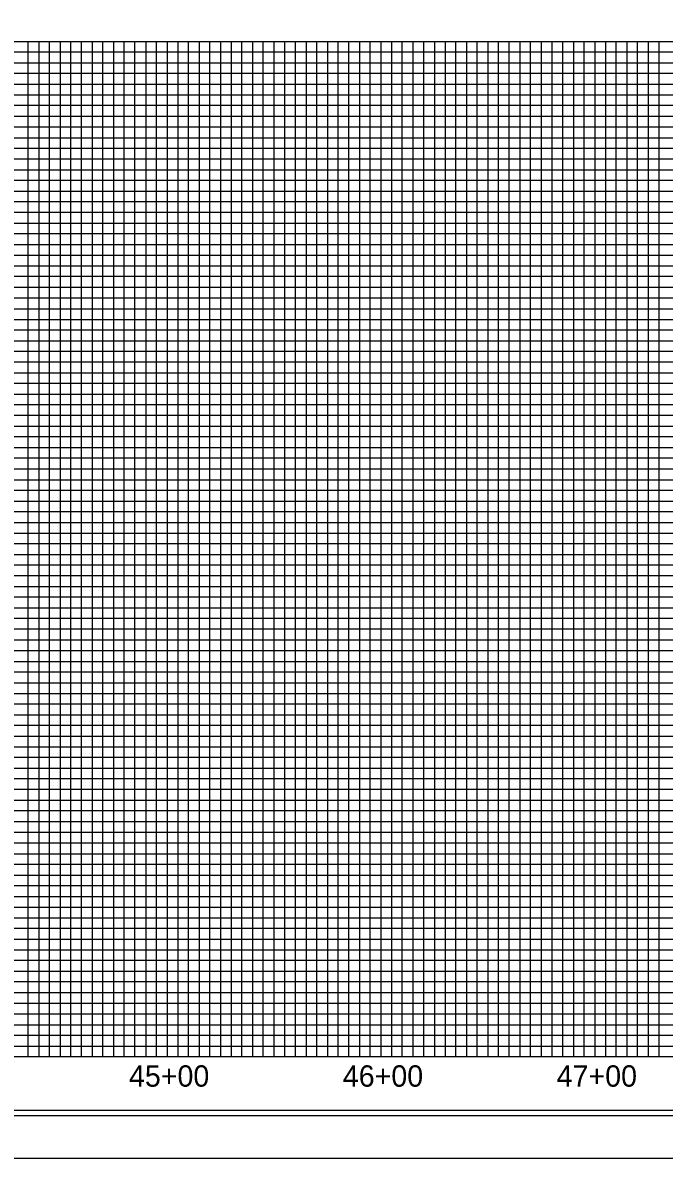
# Model space of a CAD drawing. Extents: x 0 to 7954, y -383 to 1504.
# Drawn here: x 1.851 to 2.351, y 0.008 to 0.894 of the extents above; entities that cross this region are included whole.
import ezdxf

# ---------------------------------------------------------------- set-up
doc = ezdxf.new("R2010")
doc.units = 0
for name, color, linetype in [('Sheet Profile Grid Major CELL', 7, 'Continuous'), ('Sheet Profile Grid Middle', 7, 'Continuous'), ('Sheet Profile Grid Minor CELL', 7, 'Continuous'), ('UC Plan Profile Sheet 34 CELL', 7, 'Continuous')]:
    doc.layers.add(name, color=color, linetype=linetype)

msp = doc.modelspace()

# ---------------------------------------------------------------- linework, layer by layer
at = {"layer": 'Sheet Profile Grid Major CELL'}
for points in [[(0.30499, 0.87916), (2.59666, 0.87916)], [(1.88833, 0.0875), (1.88833, 0.87916), (1.97166, 0.87916), (1.97166, 0.0875)], [(2.05499, 0.0875), (2.05499, 0.87916), (2.13833, 0.87916), (2.13833, 0.0875)], [(2.22166, 0.0875), (2.22166, 0.87916), (2.30499, 0.87916), (2.30499, 0.0875)], [(2.80499, 0.79583), (0.30499, 0.79583), (0.30499, 0.7125), (2.80499, 0.7125)], [(2.80499, 0.62916), (0.30499, 0.62916), (0.30499, 0.54583), (2.80499, 0.54583)], [(2.80499, 0.4625), (0.30499, 0.4625), (0.30499, 0.37916), (2.80499, 0.37916)], [(2.80499, 0.29583), (0.30499, 0.29583), (0.30499, 0.2125), (2.80499, 0.2125)], [(2.80499, 0.12916), (0.30499, 0.12916)]]:
    msp.add_lwpolyline(points, dxfattribs=at)
at = {"layer": 'Sheet Profile Grid Middle'}
for p, q in [((0.30499, 0.8375), (2.59666, 0.8375)), ((2.80499, 0.75416), (0.30499, 0.75416)), ((0.30499, 0.67083), (2.80499, 0.67083)), ((2.80499, 0.5875), (0.30499, 0.5875)), ((0.30499, 0.50416), (2.80499, 0.50416)), ((2.80499, 0.42083), (0.30499, 0.42083)), ((0.30499, 0.3375), (2.80499, 0.3375)), ((2.80499, 0.25416), (0.30499, 0.25416)), ((0.30499, 0.17083), (2.80499, 0.17083))]:
    msp.add_line(p, q, dxfattribs=at)
for points in [[(1.92999, 0.0875), (1.92999, 0.87916), (2.01333, 0.87916), (2.01333, 0.0875)], [(2.09666, 0.0875), (2.09666, 0.87916), (2.17999, 0.87916), (2.17999, 0.0875)], [(2.26333, 0.0875), (2.26333, 0.87916), (2.34666, 0.87916), (2.34666, 0.0875)]]:
    msp.add_lwpolyline(points, dxfattribs=at)
at = {"layer": 'Sheet Profile Grid Minor CELL'}
for points in [[(1.85499, 0.0875), (1.85499, 0.87916), (1.86333, 0.87916), (1.86333, 0.0875)], [(1.87166, 0.0875), (1.87166, 0.87916), (1.87999, 0.87916), (1.87999, 0.0875)], [(1.89666, 0.0875), (1.89666, 0.87916), (1.90499, 0.87916), (1.90499, 0.0875)], [(1.91333, 0.0875), (1.91333, 0.87916), (1.92166, 0.87916), (1.92166, 0.0875)], [(1.93833, 0.0875), (1.93833, 0.87916), (1.94666, 0.87916), (1.94666, 0.0875)], [(1.95499, 0.0875), (1.95499, 0.87916), (1.96333, 0.87916), (1.96333, 0.0875)], [(1.97999, 0.0875), (1.97999, 0.87916), (1.98833, 0.87916), (1.98833, 0.0875)], [(1.99666, 0.0875), (1.99666, 0.87916), (2.00499, 0.87916), (2.00499, 0.0875)], [(2.02166, 0.0875), (2.02166, 0.87916), (2.02999, 0.87916), (2.02999, 0.0875)], [(2.03833, 0.0875), (2.03833, 0.87916), (2.04666, 0.87916), (2.04666, 0.0875)], [(2.06333, 0.0875), (2.06333, 0.87916), (2.07166, 0.87916), (2.07166, 0.0875)], [(2.07999, 0.0875), (2.07999, 0.87916), (2.08833, 0.87916), (2.08833, 0.0875)], [(2.10499, 0.0875), (2.10499, 0.87916), (2.11333, 0.87916), (2.11333, 0.0875)], [(2.12166, 0.0875), (2.12166, 0.87916), (2.12999, 0.87916), (2.12999, 0.0875)], [(2.14666, 0.0875), (2.14666, 0.87916), (2.15499, 0.87916), (2.15499, 0.0875)], [(2.16333, 0.0875), (2.16333, 0.87916), (2.17166, 0.87916), (2.17166, 0.0875)], [(2.18833, 0.0875), (2.18833, 0.87916), (2.19666, 0.87916), (2.19666, 0.0875)], [(2.20499, 0.0875), (2.20499, 0.87916), (2.21333, 0.87916), (2.21333, 0.0875)], [(2.22999, 0.0875), (2.22999, 0.87916), (2.23833, 0.87916), (2.23833, 0.0875)], [(2.24666, 0.0875), (2.24666, 0.87916), (2.25499, 0.87916), (2.25499, 0.0875)], [(2.27166, 0.0875), (2.27166, 0.87916), (2.27999, 0.87916), (2.27999, 0.0875)], [(2.28833, 0.0875), (2.28833, 0.87916), (2.29666, 0.87916), (2.29666, 0.0875)], [(2.31333, 0.0875), (2.31333, 0.87916), (2.32166, 0.87916), (2.32166, 0.0875)], [(2.32999, 0.0875), (2.32999, 0.87916), (2.33833, 0.87916), (2.33833, 0.0875)], [(0.38833, 0.8625), (2.59666, 0.8625), (2.59666, 0.87083), (0.38833, 0.87083)], [(0.38833, 0.84583), (2.59666, 0.84583), (2.59666, 0.85416), (0.38833, 0.85416)], [(0.38833, 0.82083), (2.59666, 0.82083), (2.59666, 0.82916), (0.38833, 0.82916)], [(0.38833, 0.80416), (2.59666, 0.80416), (2.59666, 0.8125), (0.38833, 0.8125)], [(0.38833, 0.77916), (2.72166, 0.77916), (2.72166, 0.7875), (0.38833, 0.7875)], [(0.38833, 0.7625), (2.72166, 0.7625), (2.72166, 0.77083), (0.38833, 0.77083)], [(0.38833, 0.7375), (2.72166, 0.7375), (2.72166, 0.74583), (0.38833, 0.74583)], [(0.38833, 0.72083), (2.72166, 0.72083), (2.72166, 0.72916), (0.38833, 0.72916)], [(0.38833, 0.70416), (2.72166, 0.70416)], [(0.38833, 0.6875), (2.72166, 0.6875), (2.72166, 0.69583), (0.38833, 0.69583)], [(0.38833, 0.6625), (2.72166, 0.6625), (2.72166, 0.67916), (0.38833, 0.67916)], [(0.38833, 0.64583), (2.72166, 0.64583), (2.72166, 0.65416), (0.38833, 0.65416)], [(0.38833, 0.62083), (2.72166, 0.62083), (2.72166, 0.6375), (0.38833, 0.6375)], [(0.38833, 0.60416), (2.72166, 0.60416), (2.72166, 0.6125), (0.38833, 0.6125)], [(0.38833, 0.57916), (2.72166, 0.57916), (2.72166, 0.59583), (0.38833, 0.59583)], [(0.38833, 0.5625), (2.72166, 0.5625), (2.72166, 0.57083), (0.38833, 0.57083)], [(0.38833, 0.5375), (2.72166, 0.5375), (2.72166, 0.55416), (0.38833, 0.55416)], [(0.38833, 0.52083), (2.72166, 0.52083), (2.72166, 0.52916), (0.38833, 0.52916)], [(0.38833, 0.49583), (2.72166, 0.49583), (2.72166, 0.5125), (0.38833, 0.5125)], [(0.38833, 0.47916), (2.72166, 0.47916), (2.72166, 0.4875), (0.38833, 0.4875)], [(0.38833, 0.45416), (2.72166, 0.45416), (2.72166, 0.47083), (0.38833, 0.47083)], [(0.38833, 0.4375), (2.72166, 0.4375), (2.72166, 0.44583), (0.38833, 0.44583)], [(0.38833, 0.4125), (2.72166, 0.4125), (2.72166, 0.42916), (0.38833, 0.42916)], [(0.38833, 0.39583), (2.72166, 0.39583), (2.72166, 0.40416), (0.38833, 0.40416)], [(0.38833, 0.37083), (2.72166, 0.37083), (2.72166, 0.3875), (0.38833, 0.3875)], [(0.38833, 0.35416), (2.72166, 0.35416), (2.72166, 0.3625), (0.38833, 0.3625)], [(0.38833, 0.32916), (2.72166, 0.32916), (2.72166, 0.34583), (0.38833, 0.34583)], [(0.38833, 0.3125), (2.72166, 0.3125), (2.72166, 0.32083), (0.38833, 0.32083)], [(0.38833, 0.2875), (2.72166, 0.2875), (2.72166, 0.30416), (0.38833, 0.30416)], [(0.38833, 0.27083), (2.72166, 0.27083), (2.72166, 0.27916), (0.38833, 0.27916)], [(0.38833, 0.24583), (2.72166, 0.24583), (2.72166, 0.2625), (0.38833, 0.2625)], [(0.38833, 0.22916), (2.72166, 0.22916), (2.72166, 0.2375), (0.38833, 0.2375)], [(0.38833, 0.20416), (2.72166, 0.20416), (2.72166, 0.22083), (0.38833, 0.22083)], [(0.38833, 0.09583), (2.72166, 0.09583), (2.72166, 0.10416), (0.38833, 0.10416), (0.38833, 0.1125), (2.72166, 0.1125), (2.72166, 0.12083), (0.38833, 0.12083), (0.38833, 0.12916), (0.38833, 0.1375), (2.72166, 0.1375), (2.72166, 0.14583), (0.38833, 0.14583), (0.38833, 0.15416), (2.72166, 0.15416), (2.72166, 0.1625), (0.38833, 0.1625), (0.38833, 0.17083), (0.38833, 0.17916), (2.72166, 0.17916), (2.72166, 0.1875), (0.38833, 0.1875), (0.38833, 0.19583), (2.72166, 0.19583)]]:
    msp.add_lwpolyline(points, dxfattribs=at)
at = {"layer": 'UC Plan Profile Sheet 34 CELL'}
msp.add_line((2.80499, 0.0875), (0.30499, 0.0875), dxfattribs=at)
for points in [[(0.02749, 0.00833), (2.83333, 0.00833), (2.83333, 1.83333), (0.02749, 1.83333)], [(0.04916, 0.04166), (2.82583, 0.04166), (2.82583, 1.8), (0.04916, 1.8)], [(2.80499, 1.79583), (0.30499, 1.79583), (0.30499, 0.04583), (2.80499, 0.04583)], [(0.38833, 0.87916), (2.59666, 0.87916), (2.59666, 0.79583), (2.72166, 0.79583), (2.72166, 0.0875), (0.38833, 0.0875)]]:
    msp.add_lwpolyline(points, close=True, dxfattribs=at)

# ---------------------------------------------------------------- texts
for s, p in [('45+00', (1.93363, 0.06416)), ('46+00', (2.1003, 0.06416)), ('47+00', (2.26697, 0.06416))]:
    msp.add_text(s, height=0.016667, dxfattribs=at).set_placement(p)

doc.saveas('drawing.dxf')
